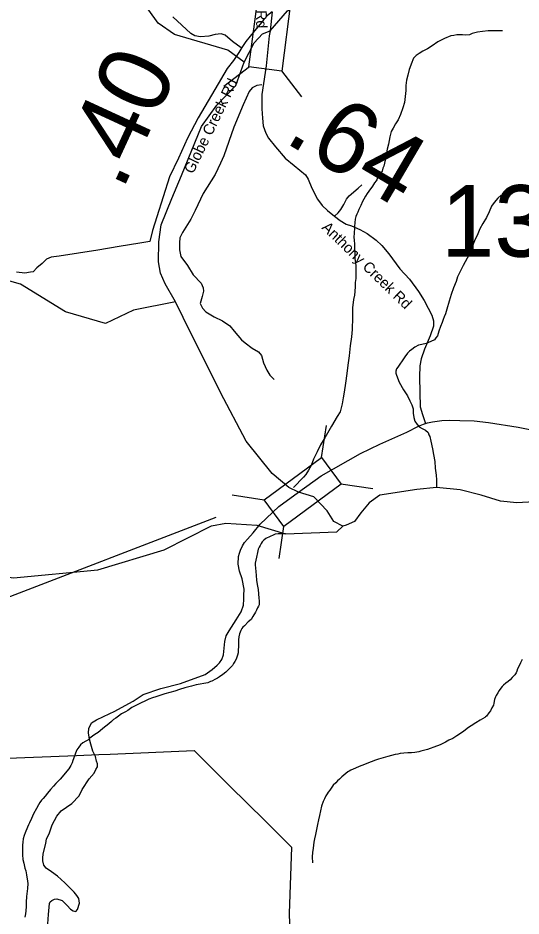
# Model space of a CAD drawing. Extents: x 1159738 to 1321356, y 736314 to 882035.
# Drawn here: x 1197770 to 1201279, y 838429 to 844699 of the extents above; entities that cross this region are included whole.
import ezdxf

# ---------------------------------------------------------------- set-up
doc = ezdxf.new("R2010")
doc.units = 0
for name, color, linetype in [('Exist Boundary Land Use Forest National US Forest Service', 7, 'Continuous'), ('Exist Hydrographic Creek Single Shore', 7, 'Continuous'), ('Exist Hydrographic Misc Water Feature', 7, 'Continuous'), ('Exist Road Non-System Type 51', 7, 'Continuous'), ('Exist Road Primary NC Attributed', 7, 'Continuous'), ('Exist Road Primary NC Structure Standard Bridge CELL', 7, 'Continuous'), ('Exist Road Primary NC Structure Standard Bridge Number Label', 7, 'Continuous'), ('Exist Road Primary NC Unpaved Attributed', 7, 'Continuous'), ('Exist Road Secondary Mileage Hundredths English Label', 7, 'Continuous'), ('Exist Road Secondary Structure Standard Bridge CELL', 7, 'Continuous'), ('Exist Road Secondary Type 41 Attributed', 7, 'Continuous'), ('Exist Road Secondary Type 51 Attributed', 7, 'Continuous'), ('Exist Road Secondary Type 51 Label', 7, 'Continuous'), ('Exist Road Secondary Type 51 Number Label', 7, 'Continuous')]:
    doc.layers.add(name, color=color, linetype=linetype)

msp = doc.modelspace()

# ---------------------------------------------------------------- linework, layer by layer
at = {"layer": 'Exist Boundary Land Use Forest National US Forest Service'}
msp.add_lwpolyline([(1197637.3, 839529.3), (1198177.8, 839550.9), (1198334.2, 839557.2), (1198412.3, 839560.2), (1198999.4, 839584.3), (1199245.4, 839339.2), (1199494.9, 839093), (1199549.4, 839039.2), (1199677.4, 838909.2), (1199661.4, 838447.3), (1199667.4, 838231.2)], dxfattribs=at)
at = {"layer": 'Exist Hydrographic Creek Single Shore'}
for points in [[(1199528.3, 844610.1), (1199649.2, 844748), (1199758.8, 844814.6), (1199876.2, 844892.9), (1199966.2, 844983), (1200040.6, 845124), (1200057.6, 845169.7)], [(1198869.3, 842716.7), (1198796, 842843.2), (1198764.7, 842917.6), (1198749, 842995.9), (1198752.9, 843136.9), (1198768.6, 843254.4), (1198842.9, 843438.5), (1198909.5, 843599.1), (1199050.3, 843941.1), (1199156, 844090), (1199289.1, 844227.1), (1199348.6, 844390.3), (1199418.2, 844524.7), (1199475.7, 844588.5), (1199528.3, 844610.1)], [(1198869.3, 842716.7), (1198576.3, 842660.2), (1198381.3, 842565.6), (1198100.3, 842646.8), (1197788.3, 842840.1), (1197242.3, 842995.5), (1196717.3, 842983), (1196369.3, 843085.1), (1196196.2, 843164.1), (1196104.3, 843159.3)], [(1199726, 841389.1), (1199658, 841420.9), (1199543.1, 841519.2), (1199361.7, 841744.8), (1199181.6, 842085.6), (1198921.2, 842608.1), (1198869.3, 842716.7)], [(1201369.6, 841321.8), (1201248.3, 841314), (1201134.8, 841325.7), (1201001.7, 841368.8), (1200853, 841404.1), (1200688.5, 841422.3), (1200551.6, 841408), (1200293.2, 841368.8), (1200218.9, 841314), (1200160.2, 841243.5), (1200117.1, 841184.7), (1200058.4, 841157.3), (1200036.4, 841150.6), (1199972.3, 841184.7), (1199925.3, 841259.2), (1199834.1, 841355.9), (1199726, 841389.1)]]:
    msp.add_lwpolyline(points, dxfattribs=at)
at = {"layer": 'Exist Hydrographic Misc Water Feature'}
for points in [[(1199348.6, 844390.3), (1199234.3, 844475.4), (1198861.3, 844584.6), (1198747.3, 844662.4), (1198498.3, 845012.1)], [(1201149, 844610), (1201092.9, 844609.6), (1201048.9, 844608.8), (1201010.8, 844605.8), (1200974.6, 844600.8), (1200938.3, 844591.7), (1200920, 844582.3), (1200893.9, 844578.9), (1200870.1, 844581.6), (1200832, 844580.6), (1200809.8, 844577.2), (1200789.8, 844573.7), (1200745.2, 844555), (1200698.6, 844532.2), (1200659.8, 844505.2), (1200625.2, 844484.2), (1200592.7, 844467.1), (1200568.3, 844451.7), (1200548, 844436.2), (1200527.5, 844418.7), (1200523, 844406.8), (1200516.6, 844389), (1200499.2, 844339.5), (1200488.2, 844299.7), (1200479.2, 844264), (1200474.1, 844228), (1200475.2, 844192), (1200470, 844150.1), (1200464.9, 844108.2), (1200453.9, 844072.5), (1200438.7, 844024.8), (1200421.6, 843987.3), (1200402.9, 843959.8), (1200386.1, 843930.2), (1200373.5, 843906.5), (1200362.4, 843868.8), (1200353.1, 843819.1), (1200344, 843783.3), (1200330.1, 843707.6), (1200320.8, 843663.8), (1200314.4, 843650), (1200309.9, 843630.1), (1200303.6, 843620.2), (1200295.3, 843606.5), (1200286.9, 843594.7), (1200278.5, 843582.9), (1200272.2, 843569), (1200268.1, 843563.2), (1200255.7, 843547.5), (1200243, 843525.8), (1200218, 843490.5), (1200205.5, 843472.8), (1200193, 843455.1), (1200182.6, 843435.4), (1200174, 843417.6), (1200161.3, 843390), (1200155, 843376.1), (1200146.6, 843362.4), (1200140.1, 843344.5), (1200133.7, 843330.7), (1200127.2, 843312.8), (1200122.7, 843294.9), (1200120, 843271), (1200117.4, 843243), (1200117, 843233), (1200114.1, 843197.1), (1200113.4, 843169.1), (1200114.7, 843147), (1200116, 843121), (1200117.1, 843092.9), (1200120.4, 843060.8), (1200119.8, 843038.8), (1200119.2, 843016.8), (1200124.5, 842992.6), (1200125.9, 842966.6), (1200127.2, 842942.5), (1200126.3, 842910.5), (1200125.6, 842880.5), (1200122.7, 842852.6), (1200122, 842824.6), (1200119.1, 842788.6), (1200116.3, 842764.7), (1200109.6, 842732.9), (1200103.9, 842675), (1200102.1, 842607), (1200101.9, 842525), (1200096.4, 842473.1), (1200086.8, 842411.3), (1200078.8, 842339.5), (1200071.1, 842275.6), (1200063.6, 842217.8), (1200053.7, 842150), (1200046, 842086.1), (1200038.9, 842048.3), (1200031.8, 842006.5), (1200025, 841976.6), (1200016.2, 841948.9), (1199995.3, 841917.4), (1199955.5, 841848.5), (1199909.3, 841767.6)], [(1201139.9, 843461.5), (1201117.3, 843442.1), (1201090.5, 843410.8), (1201073.8, 843385.3), (1201056.7, 843345.7), (1201037.7, 843306.2), (1201012.6, 843264.9), (1200991.5, 843227.3), (1200976.6, 843191.8), (1200953.2, 843142.3), (1200938.1, 843100.7), (1200918.7, 843053.2), (1200903.8, 843021.6), (1200874.4, 842970.3), (1200855.4, 842932.8), (1200836.4, 842891.3), (1200825.5, 842859.6), (1200808.2, 842816), (1200790.9, 842768.5), (1200777.7, 842722.7), (1200762.2, 842667.2), (1200751.2, 842633.4), (1200742.7, 842613.7), (1200736.2, 842593.8), (1200727.7, 842574.1), (1200716.8, 842544.3), (1200706, 842512.6), (1200697, 842480.8), (1200684.7, 842465.1), (1200674.4, 842451.4), (1200650, 842440.1), (1200617.6, 842427), (1200587.3, 842419.8), (1200563.2, 842414.4), (1200536.8, 842401.1), (1200516.5, 842385.6), (1200500.1, 842372.1), (1200487.7, 842358.4), (1200468.9, 842332.9), (1200450.3, 842305.4), (1200433.5, 842281.8), (1200419, 842262.2), (1200410.7, 842250.4), (1200406.2, 842234.5), (1200405.9, 842218.5), (1200409.4, 842204.4), (1200428.1, 842155.9), (1200458.7, 842103), (1200485.6, 842062.3), (1200502.7, 842025.8), (1200517.9, 841997.3), (1200527.2, 841971.1), (1200526.3, 841939.1), (1200531.5, 841908.9), (1200538.8, 841884.7), (1200554.2, 841860.2), (1200567.8, 841845.9), (1200589.5, 841833.2), (1200613.2, 841820.6), (1200630.7, 841804.1), (1200636.3, 841790), (1200642.1, 841777.8), (1200649.3, 841745.6), (1200661.8, 841691.2), (1200668.6, 841651), (1200677.3, 841602.8), (1200680.1, 841556.6), (1200686.7, 841506.4), (1200689.9, 841474.3), (1200688.5, 841422.3)], [(1199909.3, 841767.6), (1199880, 841718.3), (1199856.6, 841671), (1199831.2, 841619.6), (1199814, 841574), (1199797.1, 841542.5), (1199778.3, 841513), (1199761.7, 841493.4), (1199691.5, 841422.1)], [(1194931.3, 839864.1), (1195057.3, 839910.8), (1195434.3, 840257.8), (1195535.3, 840288.6), (1195676.3, 840276), (1195916.3, 840195.6), (1196084.3, 840258), (1196493.3, 840581.3), (1196729.3, 840681.7), (1197234.8, 840859.3), (1197739.4, 840789.6), (1198327.3, 840846.6), (1198789.3, 840985.1), (1199119.4, 841152.5), (1199219.3, 841173.4), (1199436.4, 841159.2), (1199634.7, 841098.9), (1199993.3, 841112), (1200036.4, 841150.6)], [(1199634.7, 841098.9), (1199584.9, 841097.9), (1199564.8, 841094.5), (1199548.7, 841088.9), (1199528.4, 841079.4), (1199498, 841064.2), (1199483.7, 841054.6), (1199473.4, 841040.9), (1199467.1, 841031.1), (1199458.7, 841017.3), (1199452.4, 841005.4), (1199446, 840989.6), (1199439.3, 840967.8), (1199432.5, 840933.9), (1199427.9, 840914), (1199425.3, 840894.1), (1199425, 840882.1), (1199427.8, 840834), (1199430.9, 840805.9), (1199434.1, 840773.8), (1199439.2, 840743.6), (1199444.4, 840709.5), (1199450.7, 840649.2), (1199452.3, 840631.2), (1199451.9, 840617.2), (1199451.4, 840603.2), (1199447.2, 840593.3), (1199440.9, 840581.5), (1199432.5, 840565.6), (1199426, 840549.9), (1199407.3, 840520.3), (1199396.7, 840500.6), (1199374.2, 840483.2), (1199349.4, 840455.8), (1199339.1, 840446.1), (1199330.9, 840436.4), (1199324.5, 840422.5), (1199315.8, 840398.7), (1199311.4, 840378.8), (1199308.7, 840356.9), (1199308.1, 840334.9), (1199307.5, 840310.9), (1199306.7, 840284.9), (1199306.5, 840274.9), (1199306.3, 840266.9), (1199301.9, 840250.9), (1199297.4, 840237.1), (1199291.1, 840223.3), (1199282.6, 840205.5), (1199274.2, 840191.7), (1199265.9, 840177.9), (1199245.3, 840156.5), (1199218.6, 840133.1), (1199198.1, 840115.7), (1199175.8, 840100.3), (1199161.5, 840090.6), (1199147.2, 840083), (1199122.8, 840069.7), (1199112.7, 840066), (1199094.4, 840058.5), (1199066.4, 840053.2), (1199040.2, 840047.9), (1199012, 840042.7), (1198979.7, 840033.5), (1198933.5, 840022.8), (1198897.1, 840011.8), (1198862.7, 839998.7), (1198828.5, 839989.6), (1198794.3, 839980.5), (1198759.8, 839969.5), (1198731.6, 839960.2), (1198707.3, 839952.9), (1198683.1, 839943.5), (1198654.7, 839930.3), (1198628.4, 839919), (1198587.9, 839898.1), (1198563.5, 839884.7), (1198534.9, 839865.4), (1198518.6, 839855.9), (1198492.2, 839840.6), (1198471.7, 839825.2), (1198453.4, 839811.6), (1198437.1, 839802.1), (1198422.7, 839788.4), (1198404.2, 839771), (1198381.8, 839755.5), (1198361.4, 839738.1), (1198342.8, 839722.6), (1198328.6, 839710.9), (1198316.4, 839703.3), (1198298.1, 839691.8), (1198271.5, 839672.4), (1198257.1, 839656.8), (1198242.9, 839649.2), (1198222.5, 839637.8), (1198206.1, 839624.2), (1198193.8, 839608.5), (1198181.2, 839590.8), (1198170.6, 839567.1), (1198157.5, 839527.5)], [(1201286.4, 840221.3), (1201275.8, 840197.5), (1201267.3, 840179.8), (1201254.7, 840156.1), (1201250.2, 840138.2), (1201243.9, 840126.4), (1201235.5, 840112.6), (1201229.2, 840106.7), (1201217, 840095.1), (1201202.5, 840079.5), (1201188.2, 840067.8), (1201171.8, 840054.3), (1201157.5, 840040.7), (1201147.1, 840030.9), (1201136.9, 840019.2), (1201126.4, 840003.5), (1201116, 839987.7), (1201105.5, 839970), (1201101.3, 839960.1), (1201094.7, 839940.3), (1201090, 839916.4), (1201085.6, 839902.5), (1201075.1, 839882.8), (1201064.6, 839863), (1201054.1, 839847.3), (1201037.5, 839825.7), (1201031.4, 839819.9), (1201025.2, 839816.1), (1200992.7, 839797), (1200962.3, 839777.8), (1200929.7, 839756.6), (1200913.3, 839745), (1200890.9, 839729.7), (1200876.5, 839718), (1200831.6, 839687.2), (1200803.1, 839670), (1200774.7, 839656.7), (1200752.4, 839643.3), (1200734.1, 839633.8), (1200713.8, 839624.4), (1200671.5, 839609.5), (1200645.2, 839598.2)], [(1200645.2, 839598.2), (1200627, 839592.7), (1200606.7, 839587.2), (1200578.6, 839580), (1200566.5, 839576.3), (1200538.4, 839571.1), (1200514.2, 839567.7), (1200488.3, 839568.4), (1200460.1, 839567.2), (1200436, 839563.8), (1200420, 839560.3), (1200399.9, 839556.8), (1200349.5, 839544.1), (1200317.1, 839533), (1200284.9, 839523.9), (1200262.7, 839518.4), (1200232.4, 839505.3), (1200167.6, 839481), (1200149.3, 839473.5), (1200125.1, 839462.2), (1200090.6, 839447.1), (1200080.5, 839441.3), (1200070.4, 839435.7), (1200056, 839424), (1200029.4, 839400.7), (1200012.9, 839385.2), (1199998.6, 839373.5), (1199986.2, 839359.8), (1199967.8, 839342.3), (1199955.3, 839322.6), (1199944.9, 839308.9), (1199934.3, 839293.2), (1199926.1, 839281.5), (1199917.7, 839267.6), (1199907.1, 839247.9), (1199898.7, 839228.1), (1199887.8, 839196.4), (1199872, 839130.7), (1199865.1, 839101), (1199858.3, 839069.1), (1199844.3, 838999.5), (1199837.5, 838967.6), (1199832.8, 838945.7), (1199827.7, 838903.8), (1199824.8, 838871.9), (1199822.1, 838843.9), (1199823, 838799.9)], [(1198157.5, 839527.5), (1198153.3, 839515.6), (1198146.7, 839499.7), (1198138.2, 839479.9), (1198123.6, 839458.3), (1198111.1, 839440.6), (1198090.5, 839415.2), (1198063.5, 839385.9), (1198034.7, 839354.6), (1198018.2, 839337.1), (1197995.6, 839313.7), (1197974.9, 839286.2), (1197958.4, 839266.6), (1197945.8, 839251), (1197933.5, 839239.3), (1197923.1, 839221.6), (1197912.6, 839205.8), (1197899.9, 839180.1), (1197878.8, 839142.7), (1197863.9, 839111.1), (1197849.2, 839079.4), (1197842.8, 839065.6), (1197836.4, 839049.8), (1197819.2, 839010.3), (1197812.9, 838992.4), (1197806.1, 838968.5), (1197803.4, 838944.6), (1197801, 838924.7), (1197800.1, 838892.7), (1197801.6, 838874.6), (1197801.1, 838856.6), (1197804.3, 838824.5), (1197811.6, 838798.3), (1197818.6, 838764.1), (1197824, 838743.9), (1197829.4, 838717.8), (1197836.2, 838673.6), (1197837.7, 838657.5), (1197836.8, 838621.5), (1197829.2, 838565.6), (1197826.2, 838525.7), (1197827.3, 838495.6), (1197824.6, 838465.7), (1197822, 838445.7), (1197817.4, 838421.9)]]:
    msp.add_lwpolyline(points, dxfattribs=at)
at = {"layer": 'Exist Road Non-System Type 51'}
for points in [[(1199326.7, 844489.7), (1199266.4, 844535.3), (1199215.4, 844579.6), (1199186, 844587.6), (1199145.8, 844584.9), (1199100.2, 844572.9), (1199042.6, 844567.5), (1199002.4, 844575.6), (1198975.6, 844591.6), (1198851, 844708.3)], [(1199471.3, 844232.3), (1199436.5, 844226.9), (1199404.3, 844212.2), (1199381.5, 844186.7), (1199341.3, 844092.8), (1199274.3, 843937.3), (1199204.7, 843736.2), (1199182.2, 843684.6), (1199144.7, 843606.9), (1199061.6, 843472.8), (1199005.3, 843354.8), (1198974.5, 843295.8), (1198916.9, 843201.9), (1198899.7, 843163.7), (1198895.7, 843128.8), (1198897, 843080.6), (1198906.4, 843035), (1198952, 842972), (1198992.1, 842904.9), (1199047.1, 842848.6), (1199060.3, 842815.8), (1199063, 842793), (1199053.6, 842755.5), (1199041.6, 842705.9), (1199057.7, 842673.7), (1199080.4, 842646.9), (1199138.1, 842612), (1199195.7, 842585.2), (1199246.6, 842549), (1199278.7, 842512.8), (1199328.3, 842452.4), (1199353.8, 842432.3), (1199403.4, 842393.4), (1199447.2, 842368.6), (1199467.3, 842343.1), (1199483.4, 842290.8), (1199504.8, 842241.2), (1199527.6, 842205), (1199557.1, 842175.5)], [(1199976.9, 843314.6), (1200003.9, 843339.8), (1200022.8, 843363.1), (1200041.8, 843396.7), (1200062.2, 843433.2), (1200079.7, 843458), (1200142.4, 843511.9), (1200168.6, 843533.8)], [(1198325.7, 843078.2), (1198057.7, 843036.2), (1198000.1, 843028.2), (1197968, 843014.8), (1197938.5, 842985.3), (1197902.3, 842954.4), (1197875.5, 842927.6), (1197858.1, 842923.6), (1197817.9, 842918.2), (1197760.3, 842923.6)]]:
    msp.add_lwpolyline(points, dxfattribs=at)
at = {"layer": 'Exist Road Primary NC Attributed'}
for points in [[(1199726, 841389.1), (1199884, 841502.4), (1200158.5, 841657.7), (1200293.3, 841723.1), (1200481.9, 841807.1), (1200564.6, 841848.9), (1200599.3, 841863), (1200612.6, 841867.9)], [(1200612.6, 841867.9), (1200626.7, 841873.1), (1200660, 841880.6), (1200725.5, 841889.1), (1200778.7, 841890.7), (1200852.7, 841890), (1200952.9, 841885.6), (1201052.6, 841876.2), (1201257.6, 841842.5), (1201424.8, 841809.5)]]:
    msp.add_lwpolyline(points, dxfattribs=at)
at = {"layer": 'Exist Road Primary NC Structure Standard Bridge CELL'}
for p, q in [((1199887.4, 841629.6), (1199921.2, 841853.4)), ((1200021.7, 841447.4), (1200245.6, 841413.6)), ((1199263.9, 841370), (1199487.7, 841336.2)), ((1199591.4, 840926), (1199625.2, 841149.8))]:
    msp.add_line(p, q, dxfattribs=at)
msp.add_lwpolyline([(1199487.7, 841336.2), (1199886.7, 841630.5), (1200024.2, 841444.1), (1199625.2, 841149.8)], close=True, dxfattribs=at)
at = {"layer": 'Exist Road Primary NC Structure Standard Bridge Number Label'}
msp.add_line((1199150.5, 841211.7), (1196104.1, 840040), dxfattribs=at)
at = {"layer": 'Exist Road Primary NC Unpaved Attributed'}
for points in [[(1197950.5, 838783.7), (1197943.3, 838814.9), (1197943.3, 838834.1), (1197944.4, 838862.9), (1197962.9, 838936), (1197969, 838967.8), (1197987.7, 839002.4), (1198008, 839066.3), (1198041.7, 839127.4), (1198071.8, 839164.6), (1198145, 839215.1), (1198195.5, 839268), (1198217.1, 839313.6), (1198266.7, 839386.9), (1198301.7, 839426), (1198313.2, 839451.6), (1198324.6, 839470.4), (1198324.6, 839490.9), (1198317.4, 839511.3), (1198310.7, 839544.4), (1198292.7, 839580.4), (1198277.1, 839628.5), (1198268.7, 839664.5), (1198261.5, 839707.8), (1198263.9, 839737.8), (1198283.1, 839778.7), (1198316.8, 839800.3), (1198365.4, 839822.6), (1198444.6, 839858.6), (1198517.9, 839898.3), (1198574.3, 839930.7), (1198644, 839976.4), (1198766.5, 840017.2), (1198904.5, 840052.2), (1199074.3, 840115.4), (1199125, 840150), (1199159.8, 840180.1), (1199175.6, 840198), (1199192.7, 840220.7), (1199204.2, 840252.2), (1199207.8, 840300.2), (1199212.6, 840347.1), (1199221, 840385.6), (1199242.7, 840421.6), (1199290.7, 840497.3), (1199325.5, 840552.6), (1199341.7, 840600.1), (1199345.3, 840641.9), (1199345.5, 840667.1), (1199347.1, 840710.4), (1199333.8, 840783.7), (1199315.9, 840838.3), (1199306.2, 840885.2), (1199307.7, 840938.6), (1199314.7, 840962.2), (1199322.8, 840982.9), (1199336.4, 841014.2), (1199350.9, 841037.5), (1199370.3, 841059.5), (1199409.9, 841104.2), (1199458.1, 841165.1), (1199589.4, 841287.7), (1199726, 841389.1)], [(1197976.9, 838375.1), (1197981.7, 838441.2), (1197990.1, 838518.1), (1197994.9, 838527.7), (1198005.7, 838538.5), (1198024.3, 838547.5), (1198041.1, 838548.7), (1198078.4, 838537.9), (1198113.2, 838503), (1198137.2, 838477.8), (1198155.2, 838465.8), (1198173.2, 838461), (1198185.3, 838474.2), (1198198.5, 838518.7), (1198194.9, 838552.3), (1198179.3, 838572.7), (1198161.2, 838596.8), (1198097.6, 838661.7), (1198045.4, 838706.7), (1198003.3, 838738), (1197966.1, 838764.4), (1197950.5, 838783.7)]]:
    msp.add_lwpolyline(points, dxfattribs=at)
at = {"layer": 'Exist Road Secondary Structure Standard Bridge CELL'}
for p, q in [((1199384, 844358.5), (1199204.5, 844220.6)), ((1199608.5, 844329.1), (1199746.4, 844149.7))]:
    msp.add_line(p, q, dxfattribs=at)
msp.add_lwpolyline([(1199673.9, 844820.6), (1199609.5, 844329), (1199379.9, 844359.1), (1199444.2, 844850.6)], close=True, dxfattribs=at)
at = {"layer": 'Exist Road Secondary Type 41 Attributed'}
msp.add_lwpolyline([(1199543, 844742.7), (1199510.9, 844717.6), (1199484.9, 844689), (1199458.2, 844657), (1199419.3, 844608.7), (1199358.4, 844535.3), (1199332, 844494), (1199310.9, 844458.8), (1199272.1, 844402.5), (1199229.6, 844346.6), (1199142, 844199), (1199027, 844002.2), (1198952.5, 843859.9), (1198888.5, 843721), (1198827.1, 843590.2), (1198737.8, 843311.8), (1198708.1, 843216.6), (1198689.7, 843137.6), (1198620.3, 843126.9), (1198476.2, 843102.9), (1198325.7, 843078.2)], dxfattribs=at)
at = {"layer": 'Exist Road Secondary Type 51 Attributed'}
for points in [[(1199543, 844742.7), (1199528.3, 844610.1)], [(1199528.3, 844610.1), (1199522.5, 844573.8), (1199500.7, 844365.9), (1199483.2, 844242.7), (1199471.6, 844165.4), (1199470.1, 844064.7), (1199474.5, 843999.1), (1199480.3, 843946.5), (1199497.8, 843895.5), (1199518.2, 843860.4), (1199564.9, 843800.6), (1199633.1, 843720.9), (1199697.3, 843669.9), (1199735.2, 843636.3), (1199774.6, 843604.2), (1199793.5, 843575), (1199819.8, 843510.8), (1199859.2, 843434.9), (1199890.9, 843389), (1199928.8, 843354), (1199976.9, 843314.6), (1200017.8, 843285.4), (1200060, 843260.6), (1200095, 843247.5), (1200154.8, 843222.7), (1200204.4, 843194.9), (1200267.1, 843148.2), (1200307.9, 843110.3), (1200356, 843051.9), (1200434.3, 842947.9), (1200499.9, 842874.9), (1200562.6, 842788.8), (1200603.4, 842726.1), (1200631.1, 842673.6), (1200657.3, 842625.4), (1200667.6, 842584.5), (1200667.6, 842546.6), (1200644.2, 842479.5), (1200604.9, 842386.9), (1200581.5, 842319.7), (1200572.8, 842271.6), (1200569.9, 842192.8), (1200572.8, 842083.4), (1200575.7, 841984.8), (1200590.3, 841930.9), (1200612.6, 841867.9)]]:
    msp.add_lwpolyline(points, dxfattribs=at)

# ---------------------------------------------------------------- texts
at = {"layer": 'Exist Road Secondary Mileage Hundredths English Label'}
for s, rotation, p in [('.40', 65.23969, (1198496.9, 843487.6)), ('.64', 329.60259, (1199616.5, 843837.9))]:
    msp.add_text(s, height=500, rotation=rotation, dxfattribs=at).set_placement(p)
at = {"layer": 'Exist Road Secondary Type 51 Label'}
for s, rotation, p in [('Anthony Creek Rd', 270.53275, (1199423.9, 845445.5)), ('Globe Creek Rd', 64.14692, (1198990.9, 843606.1)), ('Anthony Creek Rd', 315.88977, (1199883.5, 843230.9))]:
    msp.add_text(s, height=75, rotation=rotation, dxfattribs=at).set_placement(p)
at = {"layer": 'Exist Road Secondary Type 51 Number Label'}
msp.add_text('1367', height=500, dxfattribs=at).set_placement((1200720.2, 843032.4))

doc.saveas('drawing.dxf')
